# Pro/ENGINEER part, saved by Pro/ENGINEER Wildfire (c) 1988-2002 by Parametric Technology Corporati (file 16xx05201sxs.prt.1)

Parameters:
  HERSTELLER = "Hersteller"
  PSOL_NOTUSEDSKLST = "SKLST{SKETCH{NAME{"Sketch 8"}MAT{1,0,0,0,0,0,-1,0,0,1,0,0,0,-0.5,0,1}SKETCH"
  NB = "16XX05201SXS"
  NN = "16-S2"
  NT = "16 Series - Swivel - Yoke Base"
  NBSYN = "$PN.$RIGS.$T."
  LINA = "16XX05201SXS"
  PN = "16XX05201"
  RIGS = "S"
  T = "XS"
  DIA = "5"
  WIDTH = "2"
  A = "2.43750000"
  B = "3.25000000"
  C = "1.62500000"
  D = "4.00000000"
  WW1 = "2.000"
  E = "1.630"
  F = "2.600"
  H = "0.150"
  I = "0.100"
  J = "0.130"
  K = "0.310"
  T1 = "'XS','MR','PB','XA','CA','TM','NG','XI','PI','PD','XP','CH'"
  PN1 = "XS0520112"
  AXLE = "1"
  Z = "1.000"
  KT = "DUMMY"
